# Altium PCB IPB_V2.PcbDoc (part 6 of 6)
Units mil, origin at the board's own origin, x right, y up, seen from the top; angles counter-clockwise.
Board outline 14000 x 12000 mil, 6 copper layers (Top, L2 - Plane/Horiz, L3 - Horiz, L4 - Vert, L5 - Plane/Horiz, Bottom), stack 61.468 mil thick; 657 components, 436 nets, 1897 pads, 873 vias.
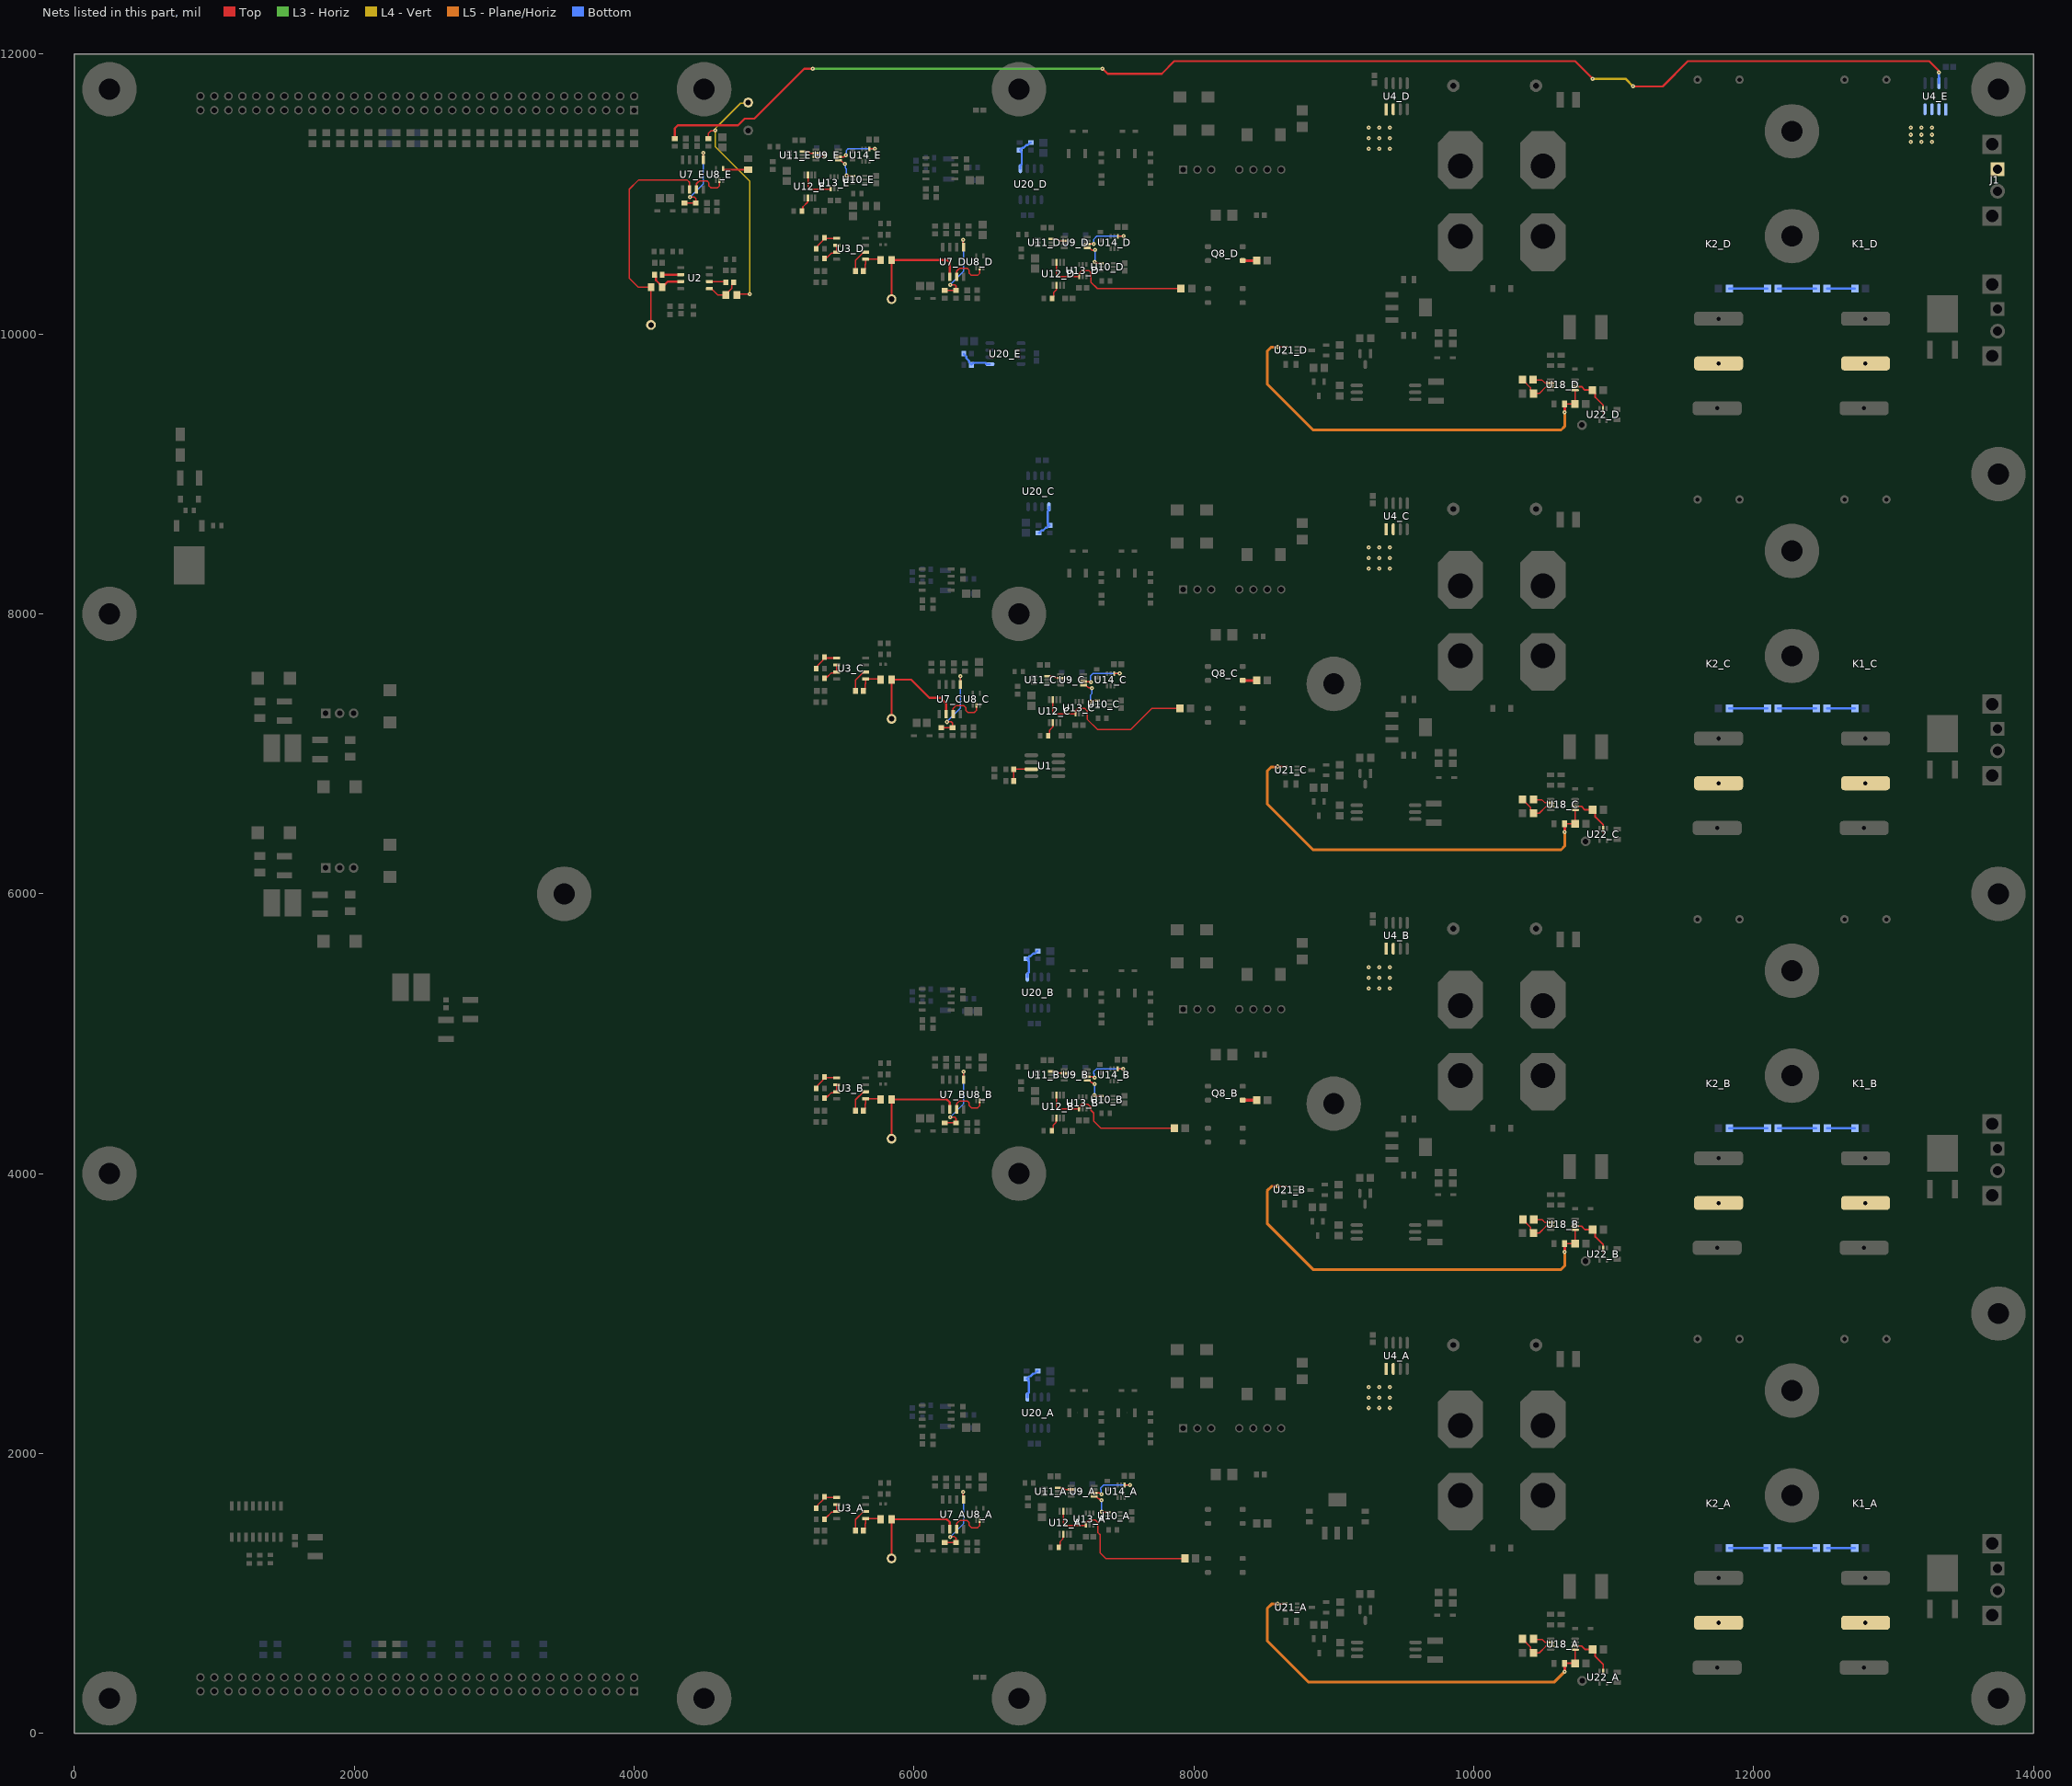
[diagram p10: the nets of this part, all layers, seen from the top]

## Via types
v1: diameter 30, hole 10, Top to Bottom, 873 vias

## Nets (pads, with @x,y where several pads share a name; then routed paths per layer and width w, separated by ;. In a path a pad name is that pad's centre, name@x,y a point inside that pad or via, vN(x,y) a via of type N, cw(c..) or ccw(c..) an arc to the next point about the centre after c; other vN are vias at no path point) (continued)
NetQ8_B_1: Q8_B.1 R83_B.1 | length 101
  Top w20: Q8_B.1@8349.02,4525 R83_B.1@8450,4525
NetQ8_C_1: Q8_C.1 R83_C.1 | length 101
  Top w20: Q8_C.1@8349.02,7525 R83_C.1@8450,7525
NetQ8_D_1: Q8_D.1 R83_D.1 | length 101
  Top w20: Q8_D.1@8349.02,10525 R83_D.1@8450,10525
NetR1_2: R1.2 R2.2 U1.3 | length 211
  Top w10: R1.2@6712.56,6805 R2.2@6712.56,6890 U1.3@6838.54,6890
NetR41_2: R41.2 U8_E.4 | length 179.4
  Top w15: U8_E.4@4635.59,11175.47 R41.2@4815,11175.47
NetR43_1: R43.1 U2.2 | length 119.4
  Top w10: U2.2@4538.35,10375 4650.63,10375 R43.1@4655.63,10370
NetR43_2: R43.2 R45.2 U2.1 | length 248.8
  Top w10: U2.1@4538.35,10325 4552.13,10325 4597.13,10280 R45.2@4655.63,10280 4655.63,10284.92 4698.03,10327.32 4698.03,10357.28 R43.2@4710.75,10370
NetR47_1: R47.1 U2.6 | length 131.5
  Top w15: R47.1@4200.12,10425 U2.6@4331.65,10425
NetR47_2: R47.2 R49.2 U2.7 | length 258.9
  Top w15: R47.2@4145,10425 4155.22,10414.78 4155.22,10384.82 R49.2@4200.12,10339.92 ; R49.2@4200.12,10335 R49.2@4200.12,10339.92 ; U2.7@4331.65,10375 4240.12,10375 4221.16,10356.04 4216.24,10356.04 R49.2@4200.12,10339.92
NetR51_A_1: R51_A.1 U3_A.2 | length 172.4
  Top w10: R51_A.1@5582.44,1450 5582.44,1527.87 5639.57,1585 U3_A.2@5653.35,1585
NetR51_A_2: R51_A.2 R53_A.2 U3_A.1 | length 200.9
  Top w10: R51_A.2@5637.56,1450 5650.27,1462.72 5650.27,1495.89 5653.35,1498.96 U3_A.1@5653.35,1535 5755.63,1535 R53_A.2@5760.63,1530
NetR51_B_1: R51_B.1 U3_B.2 | length 172.4
  Top w10: R51_B.1@5582.44,4450 5582.44,4527.87 5639.57,4585 U3_B.2@5653.35,4585
NetR51_B_2: R51_B.2 R53_B.2 U3_B.1 | length 200.9
  Top w10: R51_B.2@5637.56,4450 5650.27,4462.71 5650.27,4495.88 5653.35,4498.95 U3_B.1@5653.35,4535 5755.63,4535 R53_B.2@5760.63,4530
NetR51_C_1: R51_C.1 U3_C.2 | length 172.4
  Top w10: R51_C.1@5582.44,7450 5582.44,7527.87 5639.57,7585 U3_C.2@5653.35,7585
NetR51_C_2: R51_C.2 R53_C.2 U3_C.1 | length 200.9
  Top w10: R51_C.2@5637.56,7450 5650.27,7462.71 5650.27,7495.88 5653.35,7498.95 U3_C.1@5653.35,7535 5755.63,7535 R53_C.2@5760.63,7530
NetR51_D_1: R51_D.1 U3_D.2 | length 172.4
  Top w10: R51_D.1@5582.44,10450 5582.44,10527.87 5639.57,10585 U3_D.2@5653.35,10585
NetR51_D_2: R51_D.2 R53_D.2 U3_D.1 | length 200.9
  Top w10: R51_D.2@5637.56,10450 5650.27,10462.72 5650.27,10495.88 5653.35,10498.96 U3_D.1@5653.35,10535 5755.63,10535 R53_D.2@5760.63,10530
NetR55_A_2: R55_A.2 R56_A.2 U3_A.5 | length 193.7
  Top w10: R55_A.2@5300.47,1610 5311.22,1620.75 5311.22,1630.59 5348.78,1668.15 5348.78,1679.25 R56_A.2@5359.53,1690 5364.53,1685 U3_A.5@5446.65,1685
NetR55_B_2: R55_B.2 R56_B.2 U3_B.5 | length 193.7
  Top w10: R55_B.2@5300.47,4610 5311.22,4620.75 5311.22,4630.59 5348.78,4668.15 5348.78,4679.25 R56_B.2@5359.53,4690 5364.53,4685 U3_B.5@5446.65,4685
NetR55_C_2: R55_C.2 R56_C.2 U3_C.5 | length 193.7
  Top w10: R55_C.2@5300.47,7610 5311.22,7620.75 5311.22,7630.59 5348.78,7668.15 5348.78,7679.25 R56_C.2@5359.53,7690 5364.53,7685 U3_C.5@5446.65,7685
NetR55_D_2: R55_D.2 R56_D.2 U3_D.5 | length 193.7
  Top w10: R55_D.2@5300.47,10610 5311.22,10620.75 5311.22,10630.59 5348.78,10668.15 5348.78,10679.25 R56_D.2@5359.53,10690 5364.53,10685 U3_D.5@5446.65,10685
NetR57_A_2: R57_A.2 U3_A.6 U3_A.7 | length 162.2
  Top w10: R57_A.2@5359.53,1530 5359.53,1533.94 5370.28,1544.69 5374.21,1544.69 5408.7,1579.17 5440.83,1579.17 U3_A.7@5446.65,1585 U3_A.6@5446.65,1635
NetR57_B_2: R57_B.2 U3_B.6 U3_B.7 | length 162.2
  Top w10: R57_B.2@5359.53,4530 5359.53,4533.94 5370.28,4544.68 5374.21,4544.68 5408.7,4579.17 5440.83,4579.17 U3_B.7@5446.65,4585 U3_B.6@5446.65,4635
NetR57_C_2: R57_C.2 U3_C.6 U3_C.7 | length 162.2
  Top w10: R57_C.2@5359.53,7530 5359.53,7533.93 5370.28,7544.68 5374.21,7544.68 5408.7,7579.17 5440.83,7579.17 U3_C.7@5446.65,7585 U3_C.6@5446.65,7635
NetR57_D_2: R57_D.2 U3_D.6 U3_D.7 | length 162.2
  Top w10: R57_D.2@5359.53,10530 5359.53,10533.94 5370.28,10544.68 5374.21,10544.68 5408.7,10579.17 5440.83,10579.17 U3_D.7@5446.65,10585 U3_D.6@5446.65,10635
NetR63_A_1: R63_A.1 U12_A.3 U13_A.4 | length 1220.6
  Top w10: U12_A.3@7067.02,1586.51 7067.02,1502.98 7085,1485 7227.72,1485 U13_A.4@7229.41,1486.69 7232.13,1489.41 7232.13,1510.62 7246.5,1525 7295,1525 7315.29,1504.71 7315.29,1433.83 7330,1419.13 7330,1290 7370,1250 R63_A.1@7936.61,1250
NetR63_B_1: R63_B.1 U12_B.3 U13_B.4 | length 1081
  Top w10: U12_B.3@7017.2,4561.69 7017.2,4471.8 7027.31,4461.69 U13_B.4@7179.41,4461.69 7182.13,4464.41 7182.13,4485.62 7190.91,4494.41 7244.68,4494.41 7264.84,4474.25 7264.84,4453.45 7285,4433.29 7285,4375 7335,4325 R63_B.1@7861.61,4325
NetR63_C_1: R63_C.1 U12_C.3 U13_C.4 | length 1190.3
  Top w10: U12_C.3@6992.2,7386.69 6992.2,7296.8 7002.31,7286.69 U13_C.4@7154.41,7286.69 7157.13,7289.41 7157.13,7310.62 7172.36,7325.86 7219.14,7325.86 7237.5,7307.5 7237.5,7247.5 7310,7175 7550,7175 7700,7325 R63_C.1@7900,7325
NetR63_D_1: R63_D.1 U12_D.3 U13_D.4 | length 1106.7
  Top w10: U12_D.3@7018.74,10511.69 7018.74,10421.8 7028.84,10411.69 U13_D.4@7180.94,10411.69 ; U13_D.4@7181.65,10414.41 7181.65,10435.62 7201.03,10455 7249.53,10455 7264.76,10439.76 7264.76,10370.24 7310,10325 R63_D.1@7908.23,10325
NetR67_A_1: R67_A.1 R68_A.2 U7_A.1 | length 579.3
  Top w10: R68_A.2@6220,1362.56 R67_A.1@6300,1362.56 6300,1395 6290,1405 6261.81,1405 v1(6260,1403.19) ; v1(6350,1725) 6352.5,1722.5 6352.5,1670.85 U7_A.1@6355,1668.35
  Bottom w10: v1(6260,1403.19) 6260,1405 6355,1500 6355,1690 6350,1695 v1(6350,1725)
NetR67_B_1: R67_B.1 R68_B.2 U7_B.1 | length 582.1
  Top w10: R68_B.2@6220,4362.56 R67_B.1@6300,4362.56 6300,4395 6291.81,4403.19 v1(6260,4403.19) ; U7_B.1@6355,4668.35 v1(6355,4729.24)
  Bottom w10: v1(6260,4403.19) 6260,4405 6355,4500 v1(6355,4729.24)
NetR67_C_1: R67_C.1 R68_C.2 U7_C.1 | length 583.6
  Top w10: R68_C.2@6195,7187.56 R67_C.1@6275,7187.56 6275,7220 6265,7230 6236.81,7230 v1(6235,7228.19) ; U7_C.1@6330,7493.35 v1(6330,7554.24)
  Bottom w10: v1(6235,7228.19) 6235,7230 6330,7325 v1(6330,7554.24)
NetR67_D_1: R67_D.1 R68_D.2 U7_D.1 | length 577.8
  Top w10: R68_D.2@6220,10312.56 R67_D.1@6300,10312.56 6300,10345 6291.81,10353.19 v1(6260,10353.19) ; v1(6350,10675) 6352.5,10672.5 6352.5,10620.85 U7_D.1@6355,10618.35
  Bottom w10: v1(6260,10353.19) 6260,10355 6355,10450 6355,10640 6350,10645 v1(6350,10675)
NetR67_E_1: R67_E.1 R68_E.2 U7_E.1 | length 565.1
  Top w10: R68_E.2@4360,10937.56 R67_E.1@4440,10937.56 4440,10970 4430,10980 4401.81,10980 v1(4400,10978.19) ; U7_E.1@4495,11243.35 v1(4495,11295)
  Bottom w10: v1(4400,10978.19) 4400,10980 4495,11075 v1(4495,11295)
NetR69_E_1: R69_E.1 U4_E.7 | length 9601.7
  Top w15: R69_E.1@4290,11397.56 4290,11470 4312.5,11492.5 4742.5,11492.5 4790,11540 4858.46,11540 5215.66,11897.2 v1(5277.2,11897.2) ; v1(7347.8,11897.2) 7385,11860 7770,11860 7860,11950 10725,11950 v1(10850,11825) ; v1(11139.5,11770.5) 11350.5,11770.5 11530,11950 13255,11950 13322.32,11882.68 13322.32,11872.68 v1(13325,11870)
  L3 - Horiz w15: v1(5277.2,11897.2) v1(7347.8,11897.2)
  L4 - Vert w15: v1(10850,11825) 11085,11825 v1(11139.5,11770.5)
  Bottom w15: U4_E.7@13325,11793.06 v1(13325,11870)
NetR70_E_2: R70_E.2 U9_E.3 | length 124.5
  Top w10: U9_E.3@5298.31,11267.2 5342.11,11267.2 5354.9,11280 v1(5360.32,11280)
  Bottom w10: R70_E.2@5305,11275.47 5347.77,11275.47 5348.47,11276.17 5356.49,11276.17 v1(5360.32,11280)
NetR75_A_2: R75_A.2 U12_A.6 | length 106.8
  Top w10: R75_A.2@7034.53,1330 7045.28,1340.75 7045.28,1370.97 7065.47,1391.17 7065.47,1421.58 U12_A.6@7067.2,1423.31
NetR75_B_2: R75_B.2 U12_B.6 | length 106.8
  Top w10: R75_B.2@6984.53,4305 6995.28,4315.75 6995.28,4345.97 7015.47,4366.17 7015.47,4396.58 U12_B.6@7017.2,4398.31
NetR75_C_2: R75_C.2 U12_C.6 | length 106.8
  Top w10: R75_C.2@6959.53,7130 6970.28,7140.75 6970.28,7170.97 6990.47,7191.17 6990.47,7221.58 U12_C.6@6992.2,7223.31
NetR75_D_2: R75_D.2 U12_D.6 | length 106.8
  Top w10: R75_D.2@6986.06,10255 6996.81,10265.75 6996.81,10295.97 7017.01,10316.17 7017.01,10346.58 U12_D.6@7018.74,10348.31
NetR75_E_2: R75_E.2 U12_E.6 | length 111
  Top w10: R75_E.2@5199.53,10880 5205.67,10886.14 5205.67,10908.83 5240.47,10943.63 5240.47,10971.58 U12_E.6@5242.2,10973.31
NetR87_A_1: R87_A.1 R88_A.2 U20_A.5 | length 241.6
  Bottom w15: U20_A.5@6810.24,2402.69 6810.24,2425.24 6820,2435 6820,2514.9 6818.41,2516.5 6818.41,2523.69 6808.19,2533.91 6806.61,2533.91 6824.02,2551.31 6832.62,2551.31 6852.93,2571.62 6863.31,2571.62 6880.71,2589.03 R87_A.1@6883.66,2589.03
NetR87_B_1: R87_B.1 R88_B.2 U20_B.5 | length 241.6
  Bottom w15: U20_B.5@6810.24,5404.63 6810.24,5427.18 6820,5436.94 6820,5516.84 6818.41,5518.44 6818.41,5525.63 6808.19,5535.85 6806.61,5535.85 6824.02,5553.25 6832.62,5553.25 6852.93,5573.56 6863.31,5573.56 6880.71,5590.97 R87_B.1@6883.66,5590.97
NetR87_C_1: R87_C.1 R88_C.2 U20_C.5 | length 241.6
  Bottom w15: R87_C.1@6891.57,8578.86 6894.53,8578.86 6911.93,8596.26 6922.31,8596.26 6942.62,8616.57 6951.22,8616.57 6968.62,8633.98 6967.05,8633.98 6956.83,8644.19 6956.83,8651.39 6955.24,8652.98 6955.24,8732.88 6965,8742.65 U20_C.5@6965,8765.2
NetR87_D_1: R87_D.1 R88_D.2 U20_D.5 | length 241.6
  Bottom w15: U20_D.5@6760.24,11182.69 6760.24,11205.24 6770,11215 6770,11294.9 6768.41,11296.5 6768.41,11303.69 6758.19,11313.91 6756.61,11313.91 6774.02,11331.31 6782.62,11331.31 6802.93,11351.62 6813.31,11351.62 6830.71,11369.03 R87_D.1@6833.66,11369.03
NetR87_E_1: R87_E.1 R88_E.2 U20_E.5 | length 241.6
  Bottom w15: R87_E.1@6356.1,9858.78 6356.1,9855.83 6373.5,9838.43 6373.5,9828.05 6393.81,9807.74 6393.81,9799.14 6411.22,9781.74 6411.22,9783.31 6421.43,9793.53 6428.63,9793.53 6430.22,9795.12 6510.12,9795.12 6519.89,9785.36 U20_E.5@6542.44,9785.36
NetR94_A_1: R94_A.1 R98_A.2 U18_A.3 | length 275.5
  Top w10: R94_A.1@10350,675 10350,673.03 10405.2,617.83 10405.2,596.57 R98_A.2@10426.77,575 10468.35,575 10516.28,622.93 10548.52,622.93 U18_A.3@10550,624.41
NetR94_A_2: R94_A.2 U18_A.2 | length 133.6
  Top w10: R94_A.2@10426.77,675 10431.77,670 10490,670 10510,650 U18_A.2@10550,650
NetR94_B_1: R94_B.1 R98_B.2 U18_B.3 | length 273.4
  Top w10: R94_B.1@10350,3675.2 10350,3673.23 10405.2,3618.03 10405.2,3596.77 R98_B.2@10426.77,3575.2 10468.35,3575.2 10516.28,3623.13 U18_B.3@10548.52,3623.13
NetR94_B_2: R94_B.2 U18_B.2 | length 140.7
  Top w10: U18_B.2@10550,3650.2 10510,3650.2 10490,3670.2 R94_B.2@10431.77,3670.2 ; R94_B.2@10431.77,3670.2 10426.77,3675.2 R94_B.2@10431.77,3670.2
NetR94_C_1: R94_C.1 R98_C.2 U18_C.3 | length 275.5
  Top w10: R94_C.1@10350,6675.2 10350,6673.23 10405.2,6618.03 10405.2,6596.77 R98_C.2@10426.77,6575.2 10468.35,6575.2 10516.28,6623.13 10548.52,6623.13 U18_C.3@10550,6624.61
NetR94_C_2: R94_C.2 U18_C.2 | length 133.6
  Top w10: R94_C.2@10426.77,6675.2 10431.77,6670.2 10490,6670.2 10510,6650.2 U18_C.2@10550,6650.2
NetR94_D_1: R94_D.1 R98_D.2 U18_D.3 | length 275.5
  Top w10: R94_D.1@10350,9675.2 10350,9673.23 10405.2,9618.03 10405.2,9596.77 R98_D.2@10426.77,9575.2 10468.35,9575.2 10516.28,9623.13 10548.52,9623.13 U18_D.3@10550,9624.61
NetR94_D_2: R94_D.2 U18_D.2 | length 133.6
  Top w10: R94_D.2@10426.77,9675.2 10431.77,9670.2 10490,9670.2 10510,9650.2 U18_D.2@10550,9650.2
NetR99_A_2: R99_A.2 R100_A.2 | length 198.2
  Bottom w15: R100_A.2@12525,1325 R99_A.2@12723.23,1325
NetR99_B_2: R99_B.2 R100_B.2 | length 198.2
  Bottom w15: R100_B.2@12525,4325 R99_B.2@12723.23,4325
NetR99_C_2: R99_C.2 R100_C.2 | length 198.2
  Bottom w15: R100_C.2@12525,7325 R99_C.2@12723.23,7325
NetR99_D_2: R99_D.2 R100_D.2 | length 198.2
  Bottom w15: R100_D.2@12525,10325 R99_D.2@12723.23,10325
NetR100_A_1: R100_A.1 R101_A.1 | length 273.2
  Bottom w15: R101_A.1@12175,1325 R100_A.1@12448.23,1325
NetR100_B_1: R100_B.1 R101_B.1 | length 273.2
  Bottom w15: R101_B.1@12175,4325 R100_B.1@12448.23,4325
NetR100_C_1: R100_C.1 R101_C.1 | length 273.2
  Bottom w15: R101_C.1@12175,7325 R100_C.1@12448.23,7325
NetR100_D_1: R100_D.1 R101_D.1 | length 273.2
  Bottom w15: R101_D.1@12175,10325 R100_D.1@12448.23,10325
NetR101_A_2: R101_A.2 R103_A.2 | length 271.5
  Bottom w15: R103_A.2@11826.77,1325 R101_A.2@12098.23,1325
NetR101_B_2: R101_B.2 R103_B.2 | length 271.5
  Bottom w15: R103_B.2@11826.77,4325 R101_B.2@12098.23,4325
NetR101_C_2: R101_C.2 R103_C.2 | length 271.5
  Bottom w15: R103_C.2@11826.77,7325 R101_C.2@12098.23,7325
NetR101_D_2: R101_D.2 R103_D.2 | length 271.5
  Bottom w15: R103_D.2@11826.77,10325 R101_D.2@12098.23,10325
NetU4_E_3: U4_A.1 U4_A.2 U4_B.1 U4_B.2 U4_C.1 U4_C.2 U4_D.1 U4_D.2 U4_E.3 U4_E.4
  other v1: 9250,2325 9325,2325 9400,2325 9250,2400 9325,2400 9400,2400 9250,2475 9325,2475 9400,2475 9250,5325 9325,5325 9400,5325 9250,5400 9325,5400 9400,5400 9250,5475 9325,5475 9400,5475 9250,8325 9325,8325 9400,8325 9250,8400 9325,8400 9400,8400 9250,8475 9325,8475 9400,8475 9250,11325 9325,11325 9400,11325 13125,11375 13200,11375 13275,11375 9250,11400 9325,11400 9400,11400 13125,11425 13200,11425 13275,11425 9250,11475 9325,11475 9400,11475 13125,11475 13200,11475 13275,11475
NetU7_A_7: U7_A.7 U8_A.2 | length 294.8
  Top w10: U7_A.7@6305,1461.65 6305,1500 6325,1520 6380,1520 6395,1505 6395,1485 6410,1470 6455,1470 6470,1485 U8_A.2@6470,1529.53
NetU7_B_7: U7_B.7 U8_B.2 | length 294.8
  Top w10: U7_B.7@6305,4461.65 6305,4500 6325,4520 6380,4520 6395,4505 6395,4485 6410,4470 6455,4470 6470,4485 U8_B.2@6470,4529.53
NetU7_C_7: U7_C.7 U8_C.2 | length 294.8
  Top w10: U7_C.7@6280,7286.65 6280,7325 6300,7345 6355,7345 6370,7330 6370,7310 6385,7295 6430,7295 6445,7310 U8_C.2@6445,7354.53
NetU7_D_7: U7_D.7 U8_D.2 | length 294.8
  Top w10: U7_D.7@6305,10411.65 6305,10450 6325,10470 6380,10470 6395,10455 6395,10435 6410,10420 6455,10420 6470,10435 U8_D.2@6470,10479.53
NetU7_E_7: U7_E.7 U8_E.2 | length 294.8
  Top w10: U7_E.7@4445,11036.65 4445,11075 4465,11095 4520,11095 4535,11080 4535,11060 4550,11045 4595,11045 4610,11060 U8_E.2@4610,11104.53
NetU9_A_2: U9_A.2 U11_A.6 | length 100.4
  Top w10: U11_A.6@7028.23,1755.59 7069.33,1755.59 7082.13,1742.8 U9_A.2@7123.31,1742.8
NetU9_A_6: U9_A.6 U14_A.4 | length 362.6
  Top w10: U9_A.6@7286.69,1717.2 7328.05,1717.2 7335.22,1710.04 v1(7340.63,1710.04) ; U14_A.4@7505.59,1773.31 7507.28,1775 v1(7545,1775)
  Bottom w10: v1(7340.63,1710.04) 7336.8,1713.87 7336.8,1739.28 7335,1741.08 7335,1755 7355,1775 v1(7545,1775)
NetU9_B_2: U9_B.2 U11_B.6 | length 100.4
  Top w10: U11_B.6@6978.23,4730.59 7019.33,4730.59 7032.13,4717.8 U9_B.2@7073.31,4717.8
NetU9_B_6: U9_B.6 U14_B.4 | length 362.6
  Top w10: U9_B.6@7236.69,4692.2 7278.05,4692.2 7285.22,4685.04 v1(7290.63,4685.04) ; U14_B.4@7455.59,4748.31 7457.28,4750 v1(7495,4750)
  Bottom w10: v1(7290.63,4685.04) 7286.8,4688.87 7286.8,4714.28 7285,4716.08 7285,4730 7305,4750 v1(7495,4750)
NetU9_C_2: U9_C.2 U11_C.6 | length 100.4
  Top w10: U11_C.6@6953.23,7555.59 6994.33,7555.59 7007.13,7542.8 U9_C.2@7048.31,7542.8
NetU9_C_6: U9_C.6 U14_C.4 | length 357.2
  Top w10: U9_C.6@7211.69,7517.2 7253.05,7517.2 7258.3,7511.95 v1(7263.72,7511.95) ; U14_C.4@7430.59,7573.31 7432.28,7575 v1(7470,7575)
  Bottom w10: v1(7263.72,7511.95) 7261.8,7513.87 7261.8,7533.24 7260,7535.04 7260,7555 7280,7575 v1(7470,7575)
NetU9_D_2: U9_D.2 U11_D.6 | length 100.4
  Top w10: U11_D.6@6979.76,10680.59 7020.87,10680.59 7033.66,10667.8 U9_D.2@7074.84,10667.8
NetU9_D_6: U9_D.6 U14_D.4 | length 342
  Top w10: U9_D.6@7238.23,10642.2 7239.58,10643.56 7283.7,10643.56 v1(7285.06,10644.92) ; U14_D.4@7457.13,10698.31 7458.82,10700 v1(7496.54,10700)
  Bottom w10: v1(7285.06,10644.92) 7285.06,10678.52 7306.54,10700 v1(7496.54,10700)
NetU9_E_2: U9_E.2 U11_E.6 | length 100.4
  Top w10: U11_E.6@5203.23,11305.59 5244.33,11305.59 5257.13,11292.8 U9_E.2@5298.31,11292.8
NetU9_E_6: U9_E.6 U14_E.4 | length 339
  Top w10: U9_E.6@5461.69,11267.2 5462.21,11266.68 5499.36,11266.68 v1(5512.67,11280) ; U14_E.4@5680.59,11323.31 5682.28,11325 v1(5720,11325)
  Bottom w10: v1(5512.67,11280) 5515,11282.33 5515,11310 5530,11325 v1(5720,11325)
NetU12_E_3: U12_E.3 U13_E.4 | length 256.3
  Top w10: U12_E.3@5242.2,11136.69 5242.2,11046.8 5252.31,11036.69 U13_E.4@5404.41,11036.69
NetU22_A_2: R93_A.1 U18_A.6 U22_A.2 | length 330.5
  Top w12: U18_A.6@10725.2,624.41 10770.59,624.41 10795,600 R93_A.1@10850,600 10869.07,580.93 10869.07,548.15 10925,492.23 U22_A.2@10925,435.47
NetU22_B_2: R93_B.1 U18_B.6 U22_B.2 | length 330.5
  Top w12: U18_B.6@10725.2,3624.61 10770.59,3624.61 10795,3600.2 R93_B.1@10850,3600.2 10869.07,3581.12 10869.07,3548.35 10925,3492.43 10925,3435.67
NetU22_C_2: R93_C.1 U18_C.6 U22_C.2 | length 330.5
  Top w12: U18_C.6@10725.2,6624.61 10770.59,6624.61 10795,6600.2 R93_C.1@10850,6600.2 10869.07,6581.12 10869.07,6548.35 10925,6492.43 10925,6435.67
NetU22_D_2: R93_D.1 U18_D.6 U22_D.2 | length 330.5
  Top w12: U18_D.6@10725.2,9624.61 10770.59,9624.61 10795,9600.2 10850,9600.2 10869.07,9581.12 10869.07,9548.35 10925,9492.43 10925,9435.67
P187: J1.A U4_E.1 U4_E.2
RELAY-BOTTOM-NC_A: K2_A.4
RELAY-BOTTOM-NC_B: K2_B.4
RELAY-BOTTOM-NC_C: K2_C.4
RELAY-BOTTOM-NC_D: K2_D.4
RELAY-TOP-NC_A: K1_A.4
RELAY-TOP-NC_B: K1_B.4
RELAY-TOP-NC_C: K1_C.4
RELAY-TOP-NC_D: K1_D.4
RESETn_A: C48_A.2 R62_A.1 U18_A.5 U21_A.4 | length 2893
  Top w12: C48_A.2@10650,500 R62_A.1@10725,500 10725.2,500.2 U18_A.5@10725.2,598.82
  Top w15: v1@8599.72,925.59 U21_A.4@8659.53,925.59
  Top w20: v1@10650,440.2 C48_A.2@10650,500
  L5 - Plane/Horiz w20: v1(8599.62,925.69) 8597.71,923.78 8555.49,923.78 8525,893.28 8525,660 8820,365 10574.8,365 v1(10649.9,440.1)
RESETn_B: C48_B.2 R62_B.1 U18_B.5 U21_B.4 | length 2987.8
  Top w12: C48_B.2@10650,3500.2 R62_B.1@10725,3500.2 10725.2,3500.39 U18_B.5@10725.2,3599.02
  Top w15: v1@8598.15,3909.25 8649.29,3909.25 U21_B.4@8657.95,3909.25
  Top w20: v1@10650,3440.39 C48_B.2@10650,3500.2
  L5 - Plane/Horiz w20: v1(8598.05,3909.35) 8596.13,3907.44 8553.91,3907.44 8523.42,3876.95 8523.42,3643.66 8851.89,3315.2 10624.8,3315.2 10649.9,3340.3 v1(10649.9,3440.3)
RESETn_C: C48_C.2 R62_C.1 U18_C.5 U21_C.4 | length 2987.8
  Top w12: C48_C.2@10650,6500.2 R62_C.1@10725,6500.2 10725.2,6500.39 U18_C.5@10725.2,6599.02
  Top w15: v1@8598.15,6909.25 U21_C.4@8657.95,6909.25
  Top w20: v1@10650,6440.39 C48_C.2@10650,6500.2
  L5 - Plane/Horiz w20: v1(8598.05,6909.35) 8596.13,6907.44 8553.91,6907.44 8523.42,6876.95 8523.42,6643.66 8851.89,6315.2 10624.8,6315.2 10649.9,6340.3 v1(10649.9,6440.3)
RESETn_D: C48_D.2 R62_D.1 U18_D.5 U21_D.4 | length 3087.8
  Top w12: C48_D.2@10650,9500.2 10725,9500.2 10725.2,9500.39 U18_D.5@10725.2,9599.02
  Top w15: v1@8598.15,9909.25 U21_D.4@8657.95,9909.25
  Top w20: v1@10650,9440.39 C48_D.2@10650,9500.2
  L5 - Plane/Horiz w20: v1(8598.05,9909.35) 8596.13,9907.44 8553.91,9907.44 8523.42,9876.95 8523.42,9643.66 8851.89,9315.2 10624.8,9315.2 10649.9,9340.3 ; 10649.9,9340.3 v1(10649.9,9440.3) 10649.9,9340.3
UPSTREAM-FAULTn_A: U9_A.5 U10_A.1 | length 194.3
  Top w10: U9_A.5@7286.69,1691.61 7302.44,1691.61 7318.85,1675.21 7324.38,1675.21 7334.59,1665 v1(7340,1665) ; v1(7339,1585) 7344.41,1585 7348.82,1580.59 U10_A.1@7386.69,1580.59
  Bottom w10: v1(7339,1585) 7339.5,1585.5 7339.5,1664.5 v1(7340,1665)
UPSTREAM-FAULTn_B: U9_B.5 U10_B.1 | length 194.3
  Top w10: U9_B.5@7236.69,4666.61 7252.44,4666.61 7268.85,4650.21 7274.38,4650.21 7284.59,4640 v1(7290,4640) ; v1(7289,4560) 7294.41,4560 7298.82,4555.59 U10_B.1@7336.69,4555.59
  Bottom w10: v1(7289,4560) 7289.5,4560.5 7289.5,4639.5 v1(7290,4640)
UPSTREAM-FAULTn_C: U9_C.5 U10_C.1 | length 220.1
  Top w10: U9_C.5@7211.69,7491.61 7227.44,7491.61 7245.23,7473.83 7265.93,7473.83 v1(7269.75,7470) ; v1(7262.21,7372.79) 7267.63,7372.79 7275.43,7380.59 U10_C.1@7311.69,7380.59
  Bottom w10: v1(7262.21,7372.79) 7262.21,7421.79 7269.75,7429.33 v1(7269.75,7470)
UPSTREAM-FAULTn_D: U9_D.5 U10_D.1 | length 202.2
  Top w10: U9_D.5@7238.23,10616.61 7253.98,10616.61 7271.91,10598.68 7293.26,10598.68 v1(7295,10600.41) ; v1(7291.24,10516) 7301.65,10505.59 U10_D.1@7338.23,10505.59
  Bottom w10: v1(7291.24,10516) 7293.12,10517.88 7293.12,10598.53 v1(7295,10600.41)
UPSTREAM-FAULTn_E: U9_E.5 U10_E.1 | length 185.3
  Top w10: U9_E.5@5461.69,11241.61 5477.44,11241.61 5503.94,11215.12 v1(5505,11215.12) ; v1(5517.83,11135.12) 5521.66,11131.29 5529.95,11131.29 5530.65,11130.59 U10_E.1@5561.69,11130.59
  Bottom w10: v1(5505,11215.12) 5508.83,11211.29 5508.83,11188.19 5516.91,11180.12 5516.91,11136.04 v1(5517.83,11135.12)
V_DELAY_4: R49.1 TP3.1 U7_E.6 | length 1600.4
  Top w10: TP3.1@4120,10065 4120,10333.62 R49.1@4121.38,10335 4030,10335 3965,10400 3965,11035 4030,11100 4380,11100 4395,11085 U7_E.6@4395,11036.65
V_DELAY_A: R53_A.1 TP4_A.1 U7_A.6 | length 752.3
  Top w15: TP4_A.1@5839.37,1250 R53_A.1@5839.37,1530 6235,1530 6255,1510 U7_A.6@6255,1461.65
V_DELAY_B: R53_B.1 TP4_B.1 U7_B.6 | length 752.3
  Top w15: TP4_B.1@5839.37,4250 R53_B.1@5839.37,4530 6235,4530 6255,4510 U7_B.6@6255,4461.65
V_DELAY_C: R53_C.1 TP4_C.1 U7_C.6 | length 814.4
  Top w15: TP4_C.1@5839.37,7250 R53_C.1@5839.37,7530 5980,7530 6110,7400 6190,7400 6230,7360 U7_C.6@6230,7286.65
V_DELAY_D: R53_D.1 TP4_D.1 U7_D.6 | length 802.3
  Top w15: TP4_D.1@5839.37,10250 R53_D.1@5839.37,10530 6235,10530 6255,10510 U7_D.6@6255,10411.65
V_ISET_4: R45.1 R66_E.1 TP2.1 | length 1802.3
  Top w10: R66_E.1@4530,11397.56 4530,11434.14 4550,11454.14 4579.13,11454.14 v1(4580,11455.02) ; R45.1@4734.37,10280 4739.37,10285 v1(4825,10285) ; TP2.1@4803.5,11643.5 TP2.1@4815,11655
  L4 - Vert w10: TP2.1@4815,11655 4809.36,11649.36 4759.98,11649.36 4605.62,11495 4605,11495 4583.72,11473.72 4583.72,11458.74 v1(4580,11455.02) 4580,11340 4825,11095 v1(4825,10285)
pads on no net: MH1.1 MH2.1 MH3.1 MH4.1 MH5.1 MH6.1 MH7.1 MH9.1 MH10.1 MH13.1 MH14.1 MH15.1 MH16.1 MH17.1 MH18.1 MH19.1 MH20.1 MH21.1 MH23.1 MH25.1 MH26.1 MH27.1 MH28.1 MH29.1 PS1_A.3 PS1_A.5 PS1_A.8 PS1_B.3 PS1_B.5 PS1_B.8 PS1_C.3 PS1_C.5 PS1_C.8 PS1_D.3 PS1_D.5 PS1_D.8 U1.1 U1.4 U1.5 U1.6 U1.7 U1.8 U5.6 U6_A.2 U6_B.2 U6_C.2 U6_D.2 U8_A.1 U8_B.1 U8_C.1 U8_D.1 U8_E.1 U12_A.2 U12_B.2 U12_C.2 U12_D.2 U12_E.2 U20_A.1 U20_A.3 U20_A.7 U20_A.8 U20_B.1 U20_B.3 U20_B.7 U20_B.8 U20_C.1 U20_C.3 U20_C.7 U20_C.8 U20_D.1 U20_D.3 U20_D.7 U20_D.8 U20_E.1 U20_E.3 U20_E.7 U20_E.8 U21_A.1 U21_B.1 U21_C.1 U21_D.1 U22_A.1 U22_B.1 U22_C.1 U22_D.1

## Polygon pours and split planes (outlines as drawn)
N187 on Bottom "NONET_L-01_P-001" (solid, pour order 838): 17 vertices, not listed, extent 9195,10525 13250,11775
N187 on Bottom "NONET_L-01_P-001" (solid, pour order 837): 17 vertices, not listed, extent 9200,7525 13975,9200
N187 on Bottom "NONET_L-01_P-001" (solid, pour order 836): 17 vertices, not listed, extent 9200,4525 13975,6200
N187 on Bottom "NONET_L-01_P-001" (solid, pour order 835): 17 vertices, not listed, extent 9200,1525 13975,3200
LV_GND on Bottom "LV GND" (solid, remove dead copper, pour order 815): 43 vertices, not listed, extent 0,0 14000,12000
HV_P12V_B on Bottom "NONET_L-01_P-001" (solid, pour order 775): 17 vertices, not listed, extent 8298.43,3658.66 9773.43,5008.66
HV_P5V_D on Bottom "NONET_L-01_P-001" (solid, pour order 814): 17 vertices, not listed, extent 8525,9300 11100,10050
HV_P5V_C on Bottom "NONET_L-01_P-001" (solid, pour order 803): 17 vertices, not listed, extent 8525,6300 11100,7050
HV_P5V_B on Bottom "NONET_L-01_P-001" (solid, pour order 785): 17 vertices, not listed, extent 8525,3300 11100,4050
HV_P5V_A on Bottom "NONET_L-01_P-001" (solid, pour order 770): 21 vertices, not listed, extent 8525,300 11100,1525
NetJ5_A on Bottom "NONET_L-01_P-001" (solid, remove dead copper, pour order 680): 13100,4500 13100,3600 12250,3600 12250,3250 14000,3250 14000,3725 14000,4500 13975,4500
NetJ6_A on Bottom "NONET_L-01_P-001" (solid, remove dead copper, pour order 677): 13100,7500 13100,6600 12250,6600 12250,6250 14000,6250 14000,6725 14000,7500 13975,7500
P187 on Bottom "NONET_L-01_P-001" (solid, remove dead copper, pour order 652): 13425,11700 13425,11510 14000,11510 14000,10500 13300,10500 13300,11700
NetJ7_A on Bottom "NONET_L-01_P-001" (solid, remove dead copper, pour order 634): 13100,10450 13100,9600 12250,9600 12250,9225 14000,9225 14000,9725 14000,10450
NetJ4_A on Bottom "NONET_L-01_P-001" (solid, remove dead copper, pour order 683): 13100,1500 13100,600 12250,600 12250,225 14000,225 14000,725 14000,1500 13975,1500
HV_P12V_D on Bottom "NONET_L-01_P-001" (solid, pour order 804): 17 vertices, not listed, extent 8298.43,9658.66 9773.43,11008.66
HV_P12V_C on Bottom "NONET_L-01_P-001" (solid, pour order 793): 17 vertices, not listed, extent 8298.43,6658.66 9773.43,8008.66
HV_P12V_A on Bottom "NONET_L-01_P-001" (solid, pour order 704): 20 vertices, not listed, extent 8300,675 9775,2025
NetU4_E_3 on Bottom "NONET_L-01_P-001" (solid, remove dead copper, pour order 632): 13175,11700 13175,11510 13100,11510 13100,11300 13300,11300 13300,11700
no net on Top Overlay "NONET_L-01_P-001" (solid): 4750,9350 5850,9350 5850,9100 4750,9100
LV_GND on Top "LV GND" (solid, remove dead copper, pour order 832): 43 vertices, not listed, extent 0,0 14000,12000
ISO_RTN_A on Top "NONET_L-01_P-001" (solid, pour order 776): 10225,750 10350,750 10350,925 10740,925 10740,2550 10225,2550
NetK1_D_1 on Top "NONET_L-01_P-001" (solid, pour order 809): 10870,9925 11400,9925 11400,9875.2 13050,9875.2 13050,10425.2 10870,10425.2
COIL_DRV_HIGH_A on Top "COIL_DRV_HIGH_A_L01_P831" (solid, remove dead copper, pour order 831): 7774.96,10875 7874.96,10775 8175,10775 8175,11525 7774.96,11525
HV_P12V_D on Top "NONET_L-01_P-001" (solid, remove dead copper, pour order 828): 8275,11500 8475.39,11500 8475.39,10694.88 8275,10694.88
COIL_DRV_HIGH_A on Top "COIL_DRV_HIGH_A_L01_P827" (solid, remove dead copper, pour order 827): 7774.96,7875 7874.96,7775 8175,7775 8175,8525 7774.96,8525
HV_P12V_C on Top "NONET_L-01_P-001" (solid, remove dead copper, pour order 826): 8250.39,8544.88 8475.39,8544.88 8475.39,7694.88 8250.39,7694.88
ISO_RTN_B on Top "NONET_L-01_P-001" (solid, remove dead copper, pour order 717): 20 vertices, not listed, extent 8300,3915 9745,5575
HV_P12V_B on Top "NONET_L-01_P-001" (solid, remove dead copper, pour order 825): 8250.39,5544.88 8475.39,5544.88 8475.39,4694.88 8250.39,4694.88
COIL_DRV_HIGH_A on Top "COIL_DRV_HIGH_A_L01_P823" (solid, remove dead copper, pour order 823): 7774.96,4875 7874.96,4775 8175,4775 8175,5525 7774.96,5525
ISO_RTN_D on Top "NONET_L-01_P-001" (solid, remove dead copper, pour order 806): 20 vertices, not listed, extent 8300,9915 9745,11500
ISO_RTN_C on Top "NONET_L-01_P-001" (solid, remove dead copper, pour order 792): 20 vertices, not listed, extent 8300,6915 9745,8550
HV_P12V_A on Top "NONET_L-01_P-001" (solid, remove dead copper, pour order 720): 8250,2550 8475,2550 8475,1700 8250,1700
ISO_RTN_A on Top "NONET_L-01_P-001" (solid, remove dead copper, pour order 719): 8475,2555 8475,1705 8300,1705 8300,1555 9450,1555 9450,2245 9150,2245 9150,2555
COIL_DRV_HIGH_A on Top "COIL_DRV_HIGH_A_L01_P645" (solid, remove dead copper, pour order 645): 7790,11695 7935,11840 8680.94,11840 8680.94,11565 7790,11565
COIL_DRV_HIGH_A on Top "COIL_DRV_HIGH_A_L01_P639" (solid, remove dead copper, pour order 639): 7774.96,1875 7874.96,1775 8175,1775 8175,2525 7774.96,2525
NetJ7_A on Top "FB_Diode_1" (solid, remove dead copper, pour order 822): 13325,10000 13325,10100 13575,10100 13575,10350 13100,10350 13100,10000
NetJ6_A on Top "FB_Diode_1" (solid, remove dead copper, pour order 821): 13325,7000 13325,7100 13575,7100 13575,7350 13100,7350 13100,7000
NetJ5_A on Top "FB_Diode_1" (solid, remove dead copper, pour order 820): 13325,4000 13325,4100 13575,4100 13575,4350 13100,4350 13100,4000
NetJ7_B on Top "NONET_L-01_P-001" (solid, remove dead copper, pour order 819): 13750,10100 13500,10100 13500,9925 13125,9925 13125,9700 11400,9700 11400,9225 14000,9225 14000,10100
NetJ6_B on Top "NONET_L-01_P-001" (solid, remove dead copper, pour order 818): 13750,7100 13500,7100 13500,6925 13125,6925 13125,6700 11400,6700 11400,6250 14000,6250 14000,7100
NetJ5_B on Top "NONET_L-01_P-001" (solid, remove dead copper, pour order 817): 13750,4100 13500,4100 13500,3925 13125,3925 13125,3700 11400,3700 11400,3250 14000,3250 14000,4100
NetJ4_B on Top "NONET_L-01_P-001" (solid, remove dead copper, pour order 714): 13750,1100 13500,1100 13500,925 13125,925 13125,700 11400,700 11400,175 14000,175 14000,1100
NetJ4_A on Top "FB_Diode_1" (solid, remove dead copper, pour order 679): 13325,1000 13325,1100 13575,1100 13575,1350 13100,1350 13100,1000
LV_P5V on Top "NONET_L-01_P-001" (solid, remove dead copper, pour order 638): 1450,1500 1450,1375 1950,1375 1950,1500
ISO_RTN_D on Top "NONET_L-01_P-001" (solid, pour order 816): 9498.43,9543.66 9498.43,9358.66 9798.43,9358.66 9798.43,9543.66
HV_P12V_D on Top "NONET_L-01_P-001" (solid, pour order 811): 9498.43,9623.66 9798.43,9623.66 9798.43,9758.66 9648.43,9758.66 9648.43,9833.66 9498.43,9833.66
ISO_RTN_D on Top "NONET_L-01_P-001" (solid, pour order 808): 10225,9750 10350,9750 10350,9925 10740,9925 10740,11550 10225,11550
NetC59_D_1 on Top "DRAIN_B" (solid, remove dead copper, pour order 807): 9570,11700 9570,11540 10165,11540 10165,10950 9450,10950 9450,11125 9450,11700
NetK1_C_1 on Top "NONET_L-01_P-001" (solid, pour order 799): 10870,6925 11400,6925 11400,6875.2 13050,6875.2 13050,7425.2 10870,7425.2
ISO_RTN_C on Top "NONET_L-01_P-001" (solid, pour order 798): 9498.43,6543.66 9498.43,6358.66 9798.43,6358.66 9798.43,6543.66
HV_P12V_C on Top "NONET_L-01_P-001" (solid, pour order 797): 9498.43,6623.66 9798.43,6623.66 9798.43,6758.66 9648.43,6758.66 9648.43,6833.66 9498.43,6833.66
ISO_RTN_C on Top "NONET_L-01_P-001" (solid, pour order 796): 10225,6750 10350,6750 10350,6925 10740,6925 10740,8550 10225,8550
NetC59_C_1 on Top "DRAIN_B" (solid, remove dead copper, pour order 795): 9570,8675 9570,8540 10165,8540 10165,7950 9450,7950 9450,8125 9450,8675
HV_P5V_D on Top "NONET_L-01_P-001" (solid, pour order 791): 9535.91,10140 9335.91,10140 9335.91,10015 9435.91,9915 9535.91,9915
HV_P12V_D on Top "NONET_L-01_P-001" (solid, pour order 790): 9335.91,10365 9435.91,10465 9535.91,10465 9535.91,10240 9335.91,10240
HV_P5V_C on Top "NONET_L-01_P-001" (solid, pour order 789): 9535.91,7140 9335.91,7140 9335.91,7015 9435.91,6915 9535.91,6915
HV_P12V_C on Top "NONET_L-01_P-001" (solid, pour order 788): 9335.91,7365 9435.91,7465 9535.91,7465 9535.91,7240 9335.91,7240
HV_P12V_B on Top "NONET_L-01_P-001" (solid, pour order 784): 9335.91,4365 9435.91,4465 9535.91,4465 9535.91,4240 9335.91,4240
HV_P5V_B on Top "NONET_L-01_P-001" (solid, pour order 787): 9535.91,4140 9335.91,4140 9335.91,4015 9435.91,3915 9535.91,3915
ISO_RTN_B on Top "NONET_L-01_P-001" (solid, pour order 783): 9498.43,3543.66 9498.43,3358.66 9798.43,3358.66 9798.43,3543.66
HV_P12V_B on Top "NONET_L-01_P-001" (solid, pour order 782): 9498.43,3623.66 9798.43,3623.66 9798.43,3758.66 9648.43,3758.66 9648.43,3833.66 9498.43,3833.66
NetK1_B_1 on Top "NONET_L-01_P-001" (solid, pour order 781): 10870,3925 11400,3925 11400,3875.2 13050,3875.2 13050,4425.2 10870,4425.2
ISO_RTN_B on Top "NONET_L-01_P-001" (solid, pour order 778): 10225,3750 10350,3750 10350,3925 10740,3925 10740,5550 10225,5550
NetK1_A_1 on Top "NONET_L-01_P-001" (solid, pour order 777): 10870,925 11400,925 11400,875 13050,875 13050,1425 10870,1425
ISO_RTN_A on Top "NONET_L-01_P-001" (solid, pour order 774): 9500,560 9500,375 9800,375 9800,560
HV_P5V_A on Top "NONET_L-01_P-001" (solid, pour order 773): 9075,1550 9075,1350 9200,1350 9300,1450 9300,1550
HV_P12V_A on Top "NONET_L-01_P-001" (solid, pour order 772): 8850,1350 8750,1450 8750,1550 8975,1550 8975,1350
HV_P12V_A on Top "NONET_L-01_P-001" (solid, pour order 761): 9500,640 9800,640 9800,775 9650,775 9650,850 9500,850
NetU4_E_3 on Top "NONET_L-01_P-001" (solid, remove dead copper, pour order 675): 9330,2675 9330,2540 9200,2540 9200,2300 9450,2300 9450,2675
NetC59_A_1 on Top "DRAIN_A" (solid, remove dead copper, pour order 692): 9570,2675 9570,2540 10150,2540 10150,1950 9450,1950 9450,2125 9450,2675
COIL_RTN_HIGH_D on Top "COIL_RTN_HIGH_D_L01_P724" (solid, remove dead copper, pour order 724): 7600,11225 7600,11335 7750,11335 7750,11500 7530,11500 7530,11400 7480,11400 7480,11225
COIL_DRV_HIGH_A on Top "COIL_DRV_HIGH_A_L01_P630" (solid, remove dead copper, pour order 630): 7530,11500 7530,11400 7375,11400 7375,11500
NetC59_B_1 on Top "DRAIN_B" (solid, remove dead copper, pour order 693): 9570,5675 9570,5540 10165,5540 10165,4950 9450,4950 9450,5125 9450,5675
NetU4_E_3 on Top "NONET_L-01_P-001" (solid, remove dead copper, pour order 691): 9330,11700 9330,11540 9200,11540 9200,11300 9445,11300 9445,11700
CGND on Top "FB-CGND-2" (solid, remove dead copper, pour order 752): 6469.8,500 6350,500 6350,0 6469.8,0
CGND on Top "FB-CGND-1" (solid, remove dead copper, pour order 751): 6469.8,12000 6350,12000 6350,11500 6469.8,11500
LV_P5V on Top "NONET_L-01_P-001" (solid, remove dead copper, pour order 647): 1945,7315 1945,7355 2060,7355 2060,7315 2395,7315 2395,6665 2145,6665 2145,7065 2070,7065 2070,7165 1845,7165 1845,7315
LV_GND on Top "NONET_L-01_P-001" (solid, remove dead copper, pour order 648): 1945,7330 1945,7355 2060,7355 2060,7330 2360,7330 2360,7645 1420,7645 1420,7330 1630,7330 1630,7355 1835,7355 1835,7330
NetC43_1 on Top "NONET_L-01_P-001" (solid, remove dead copper, pour order 649): 1420,7640 1195,7640 1195,7315 1420,7315
NetC46_2 on Top "NONET_L-01_P-001" (solid, remove dead copper, pour order 650): 1620,7355 1845,7355 1845,7146.3 2045,7146.3 2045,7040 1670,7040 1670,6890 1485,6890 1485,7180 1620,7180
LV_GND on Top "NONET_L-01_P-001" (solid, remove dead copper, pour order 651): 1670,7040 1895,7040 1895,6670.51 1670,6670.51 1670,6665
NetC44_1 on Top "NONET_L-01_P-001" (solid, remove dead copper, pour order 653): 1895,7040 1895,6665 2120,6665 2120,7040 2095,7040
LV_P12V on Top "NONET_L-01_P-001" (solid, remove dead copper, pour order 654): 2399.84,5170 2150,5170 2150,5560 2149.84,5560 2149.84,5960 2074.84,5960 2074.84,6060 1849.84,6060 1849.84,6210 1949.84,6210 1949.84,6250 2064.84,6250 2064.84,6210 2399.84,6210
LV_GND on Top "NONET_L-01_P-001" (solid, remove dead copper, pour order 655): 1949.84,6225 1949.84,6250 2064.84,6250 2064.84,6225 2364.84,6225 2364.84,6540 1424.84,6540 1424.84,6225 1634.84,6225 1634.84,6250 1839.84,6250 1839.84,6225
NetC53_1 on Top "NONET_L-01_P-001" (solid, remove dead copper, pour order 656): 1424.84,6535 1199.84,6535 1199.84,6210 1424.84,6210
NetC56_2 on Top "NONET_L-01_P-001" (solid, remove dead copper, pour order 657): 1624.84,6250 1849.84,6250 1849.84,6041.3 2049.84,6041.3 2049.84,5935 1674.84,5935 1674.84,5785 1489.84,5785 1489.84,6075 1624.84,6075
LV_GND on Top "NONET_L-01_P-001" (solid, remove dead copper, pour order 658): 1674.84,5935 1899.84,5935 1899.84,5565.51 1674.84,5565.51 1674.84,5560
NetC54_1 on Top "NONET_L-01_P-001" (solid, remove dead copper, pour order 659): 1899.84,5935 1899.84,5560 2124.84,5560 2124.84,5935 2099.84,5935
NetU4_E_3 on Top "NONET_L-01_P-001" (solid, remove dead copper, pour order 676): 9330,5675 9330,5540 9200,5540 9200,5300 9450,5300 9450,5675
NetU4_E_3 on Top "NONET_L-01_P-001" (solid, remove dead copper, pour order 678): 9330,8675 9330,8540 9200,8540 9200,8300 9450,8300 9450,8675
COIL_RTN_LOW_D on Top "COIL_RTN_LOW_D_L01_P721" (solid, remove dead copper, pour order 721): 7244.8,11225 7244.8,11335 7390,11335 7390,11500 7180,11500 7180,11400 7136.5,11400 7136.5,11225
COIL_RTN_LOW_D on Top "COIL_RTN_LOW_D_L01_P722" (solid, remove dead copper, pour order 722): 7123.5,11225 7136.5,11225 7136.5,11400 7123.5,11400
COIL_DRV_HIGH_A on Top "COIL_DRV_HIGH_A_L01_P723" (solid, remove dead copper, pour order 723): 7180,11500 7180,11400 7050,11400 7050,11500
COIL_RTN_LOW_C on Top "COIL_RTN_LOW_C_L01_P725" (solid, remove dead copper, pour order 725): 7244.8,8225 7244.8,8330 7390,8330 7390,8500 7180,8500 7180,8400 7135,8400 7135,8225
COIL_DRV_HIGH_A on Top "COIL_DRV_HIGH_A_L01_P726" (solid, remove dead copper, pour order 726): 7180,8500 7180,8400 7050,8400 7050,8500
COIL_RTN_HIGH_C on Top "COIL_RTN_HIGH_C_L01_P727" (solid, remove dead copper, pour order 727): 7600,8225 7600,8335 7750,8335 7750,8500 7530,8500 7530,8400 7485,8400 7485,8225
COIL_DRV_HIGH_A on Top "COIL_DRV_HIGH_A_L01_P728" (solid, remove dead copper, pour order 728): 7530,8500 7530,8400 7375,8400 7375,8500
COIL_RTN_LOW_B on Top "COIL_RTN_LOW_B_L01_P729" (solid, remove dead copper, pour order 729): 7244.8,5225 7244.8,5330 7390,5330 7390,5500 7180,5500 7180,5400 7135,5400 7135,5225
COIL_DRV_HIGH_A on Top "COIL_DRV_HIGH_A_L01_P730" (solid, remove dead copper, pour order 730): 7180,5500 7180,5400 7050,5400 7050,5500
COIL_RTN_HIGH_B on Top "COIL_RTN_HIGH_B_L01_P731" (solid, remove dead copper, pour order 731): 7600,5225 7600,5330 7750,5330 7750,5500 7530,5500 7530,5400 7485,5400 7485,5225
COIL_DRV_HIGH_A on Top "COIL_DRV_HIGH_A_L01_P732" (solid, remove dead copper, pour order 732): 7530,5500 7530,5400 7400,5400 7400,5500
COIL_RTN_LOW_A on Top "COIL_RTN_LOW_A_L01_P733" (solid, remove dead copper, pour order 733): 7244.8,2225 7244.8,2330 7390,2330 7390,2500 7180,2500 7180,2400 7135,2400 7135,2225
COIL_DRV_HIGH_A on Top "COIL_DRV_HIGH_A_L01_P737" (solid, remove dead copper, pour order 737): 7180,2500 7180,2400 7050,2400 7050,2500
COIL_RTN_HIGH_A on Top "COIL_RTN_HIGH_A_L01_P738" (solid, remove dead copper, pour order 738): 7600,2225 7600,2335 7750,2335 7750,2500 7530,2500 7530,2400 7485,2400 7485,2225
COIL_DRV_HIGH_A on Top "COIL_DRV_HIGH_A_L01_P739" (solid, remove dead copper, pour order 739): 7530,2500 7530,2400 7400,2400 7400,2500
NetC13_2 on Top "NONET_L-01_P-001" (solid, remove dead copper, pour order 740): 620,9210 820,9210 820,8540 620,8540
NetC13_1 on Top "NONET_L-01_P-001" (solid, remove dead copper, pour order 741): 818.12,9211.55 1020,9211.55 1020,8541.55 818.12,8541.55 818.12,8551.55
COIL_DRV_HIGH_A on Top "Top-SYS_24V" (solid, remove dead copper, pour order 742): 17 vertices, not listed, extent 620,5780 1624.84,8540
LV_ISNS_P12V on Top "NONET_L-01_P-001" (solid, remove dead copper, pour order 743): 2410,5160 2410,5480 3010,5480 3010,5160
LV_IGB_P24V on Top "NONET_L-01_P-001" (solid, remove dead copper, pour order 744): 620,9210 620,11890 1390,11890 1390,9850 1020,9480 1020,9210
NetFB2_2 on Top "MH_CGND_CONNECT_MH11" (solid, remove dead copper, pour order 749): 6480,12000 6480,11500 7025,11500 7025,12000
NetFB1_2 on Top "MH_CGND_CONNECT_MH8" (solid, remove dead copper, pour order 750): 6480,500 6480,0 7025,0 7025,500
NetU4_E_3 on L5 - Plane/Horiz "NONET_L-01_P-001" (solid, remove dead copper, pour order 625): 35 vertices, not listed, extent 9200,0 14000,11700
LV_GND on L5 - Plane/Horiz "LV GND" (solid, remove dead copper, pour order 748): 43 vertices, not listed, extent 0,0 14000,12000
ISO_RTN_D on L5 - Plane/Horiz "NONET_L-01_P-001" (solid, remove dead copper, pour order 813): 10210,11450 10210,9905 11200,9905 11200,9255 8275,9255 8275,10550 8275,11500 9175,11500 9175,11250 9500,11250 9500,11450
ISO_RTN_C on L5 - Plane/Horiz "NONET_L-01_P-001" (solid, remove dead copper, pour order 802): 10210,8450 10210,6905 11200,6905 11200,6255 8275,6255 8275,7550 8275,8550 9175,8550 9175,8250 9500,8250 9500,8450
ISO_RTN_B on L5 - Plane/Horiz "NONET_L-01_P-001" (solid, remove dead copper, pour order 801): 10210,5450 10210,3905 11200,3905 11200,3250 8275,3250 8275,5550 9150,5550 9150,5250 9500,5250 9500,5450
ISO_RTN_A on L5 - Plane/Horiz "NONET_L-01_P-001" (solid, remove dead copper, pour order 670): 10210,2450 10210,905 11200,905 11200,25 8275,25 8275,1550 8275,2550 9150,2550 9150,2250 9500,2250 9500,2450
LV_GND on L2 - Plane/Horiz "LV GND" (solid, remove dead copper, pour order 746): 43 vertices, not listed, extent 0,0 14000,12000
ISO_RTN_D on L2 - Plane/Horiz "NONET_L-01_P-001" (solid, pour order 812): 10150,9900 11225,9900 11225,9225 8275,9225 8275,11510 9200,11510 9200,10900 10150,10900
ISO_RTN_C on L2 - Plane/Horiz "NONET_L-01_P-001" (solid, pour order 800): 10150,6900 11225,6900 11225,6250 8300,6250 8300,8510 9200,8510 9200,7900 10150,7900
ISO_RTN_B on L2 - Plane/Horiz "NONET_L-01_P-001" (solid, pour order 786): 10150,3985 10235,3900 11225,3900 11225,3250 8275,3250 8275,5510 9200,5510 9200,4900 10150,4900
ISO_RTN_A on L2 - Plane/Horiz "NONET_L-01_P-001" (solid, pour order 769): 10150,900 11200,900 11200,25 8275,25 8275,2525 8300,2550 9200,2550 9200,1900 10150,1900
N187 on L2 - Plane/Horiz "NONET_L-01_P-001" (solid, pour order 780): 51 vertices, not listed, extent 9250,174.6 14000,11775
CGND on L4 - Vert "NONET_L-01_P-001" (solid, remove dead copper, pour order 768): 20 vertices, not listed, extent 8300,0 14000,11675
LV_GND on L4 - Vert "LV GND" (solid, remove dead copper, pour order 762): 43 vertices, not listed, extent -50,-7.5 13950,11992.5
COIL_DRV_HIGH_A on L4 - Vert "COIL_DRV_HIGH_A_L04_P736" (solid, remove dead copper, pour order 736): 60 vertices, not listed, extent 625,50 8150,11525
LV_ISNS_P12V on L4 - Vert "NONET_L-01_P-001" (solid, remove dead copper, pour order 745): 33 vertices, not listed, extent 2400,525 7625,11100
CGND on L3 - Horiz "NONET_L-01_P-001" (solid, remove dead copper, pour order 756): 21 vertices, not listed, extent 5750,0 14000,12000
LV_GND on L3 - Horiz "LV GND" (solid, remove dead copper, pour order 759): 37 vertices, not listed, extent 0,0 13025,12000
LV_P5V on L3 - Horiz "L3 - Horiz-LV_P5V" (solid, remove dead copper, pour order 747): 53 vertices, not listed, extent 1825,800 7609.35,11450

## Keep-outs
Keep-Out Layer:
  circle w40: c250,4000 r220
  circle w40: c250,8000 r220
  circle w40: c9000,7500 r220
  circle w40: c250,250 r220
  circle w40: c250,11750 r220
  circle w40: c4500,11750 r220
  circle w40: c6750,8000 r220
  circle w40: c3500,6000 r220
  circle w40: c6750,4000 r220
  circle w40: c4500,250 r220
  circle w40: c12275,8450 r220
  circle w40: c12275,11450 r220
  circle w40: c12275,10700 r220
  circle w40: c12275,7700 r220
  circle w40: c13750,3000 r220
  circle w40: c9000,4500 r220
  circle w40: c12275,4700 r220
  circle w40: c13750,6000 r220
  circle w40: c13750,9000 r220
  circle w40: c13750,11750 r220
  circle w40: c12275,5450 r220
  circle w40: c12275,1700 r220
  circle w40: c12275,2450 r220
  circle w40: c13750,250 r220

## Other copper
Top:
  pour cut-out: 282.21,6482.21 282.21,5875 142.79,5875 142.79,6482.21
  text "1" at 175,6450 h40 r270
L2 - Plane/Horiz:
  pour cut-out: 282.21,6482.21 282.21,5875 142.79,5875 142.79,6482.21
  text "2" at 175,6375.03 h40 r270
L3 - Horiz:
  pour cut-out: 282.21,6482.21 282.21,5875 142.79,5875 142.79,6482.21
  text "3" at 175.43,6275 h40 r270
L5 - Plane/Horiz:
  pour cut-out: 282.21,6482.21 282.21,5875 142.79,5875 142.79,6482.21
  text "5" at 175.43,6075 h40 r270
L4 - Vert:
  pour cut-out: 282.21,6482.21 282.21,5875 142.79,5875 142.79,6482.21
  text "4" at 175,6175 h40 r270
Bottom:
  pour cut-out: 282.21,6482.21 282.21,5875 142.79,5875 142.79,6482.21
  text "6" at 175.43,5975 h40 r270

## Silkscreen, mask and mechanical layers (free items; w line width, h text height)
Top Overlay:
  text "INSTRUMENT POWER BOARD" at 4525,9600.43 h40
  text "PN: .Gbl_PCB_DWG_NO REV: .Gbl_Revision" at 4525,9500.43 h40
  text "BSALMI AUG 2024 UW-APL" at 4525,9400.43 h40
  text "SN:" at 4525,9300.43 h40
Mechanical 1:
  the board outline again, w10
Mechanical 13:
Mechanical 15:
  text "P187" at 22809.72,22829.63 h400
  text "N187" at 22800,21343.91 h400
  text "P187" at 22809.72,19858.2 h400
  text "N187" at 22800,18372.48 h400
  text "P187" at 22809.72,16886.77 h400
  text "N187" at 22800,15401.06 h400
  text "P187" at 22809.72,13915.34 h400
  text "N187" at 22800,12429.63 h400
